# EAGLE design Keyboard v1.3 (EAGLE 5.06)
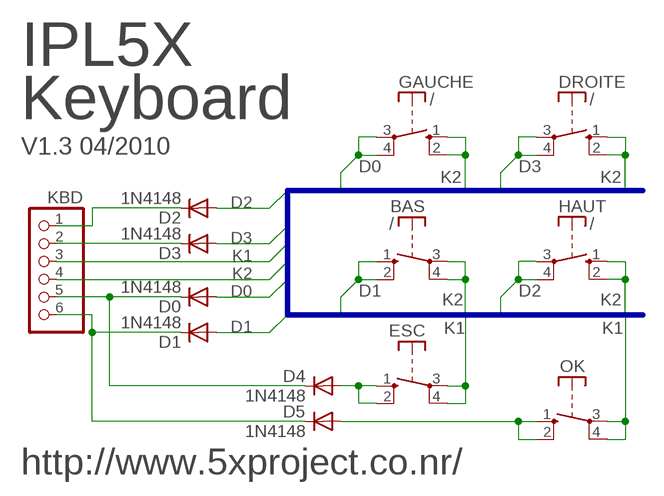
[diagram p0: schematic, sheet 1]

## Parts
BAS  /  RACON12/  [RACON12/]
D0  1N4148  1N4148DO35-7  [DO35-7]
D1  1N4148  1N4148DO35-7  [DO35-7]
D2  1N4148  1N4148DO35-7  [DO35-7]
D3  1N4148  1N4148DO35-7  [DO35-7]
D4  1N4148  1N4148DO35-7  [DO35-7]
D5  1N4148  1N4148DO35-7  [DO35-7]
DROITE  /  RACON12/  [RACON12/]
ESC  RACON12  [RACON12]
GAUCHE  /  RACON12/  [RACON12/]
HAUT  /  RACON12/  [RACON12/]
KBD  PINHD-1X6  [1X06]
OK  RACON12  [RACON12]

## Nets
D0: D0.A GAUCHE.3(P) GAUCHE.4(P)
D1: BAS.1(S) BAS.2(S) D1.A
D2: D2.A HAUT.3(P) HAUT.4(P)
D3: D3.A DROITE.3(P) DROITE.4(P)
K1: ESC.3(P) ESC.4(P) KBD.3 OK.3(P) OK.4(P)
K2: BAS.3(P) BAS.4(P) DROITE.1(S) DROITE.2(S) GAUCHE.1(S) GAUCHE.2(S) HAUT.1(S) HAUT.2(S) KBD.4
N$2: D1.C D5.C KBD.6
N$3: D0.C D4.C KBD.5
N$4: D3.C KBD.2
N$5: D2.C KBD.1
N$6: D4.A ESC.1(S) ESC.2(S)
N$7: D5.A OK.1(S) OK.2(S)

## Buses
D0,D1,D2,D3,E,RS,K1,K2

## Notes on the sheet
- IPL5X
- Keyboard
- V1.3 04/2010
- http://www.5xproject.co.nr/

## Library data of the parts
BAS DROITE ESC GAUCHE HAUT OK = switch-misc:RACON12: ITT SWITCH
D0 D1-D5 = diode:1N4148: DIODE
KBD = pinhead:PINHD-1X6: PIN HEADER

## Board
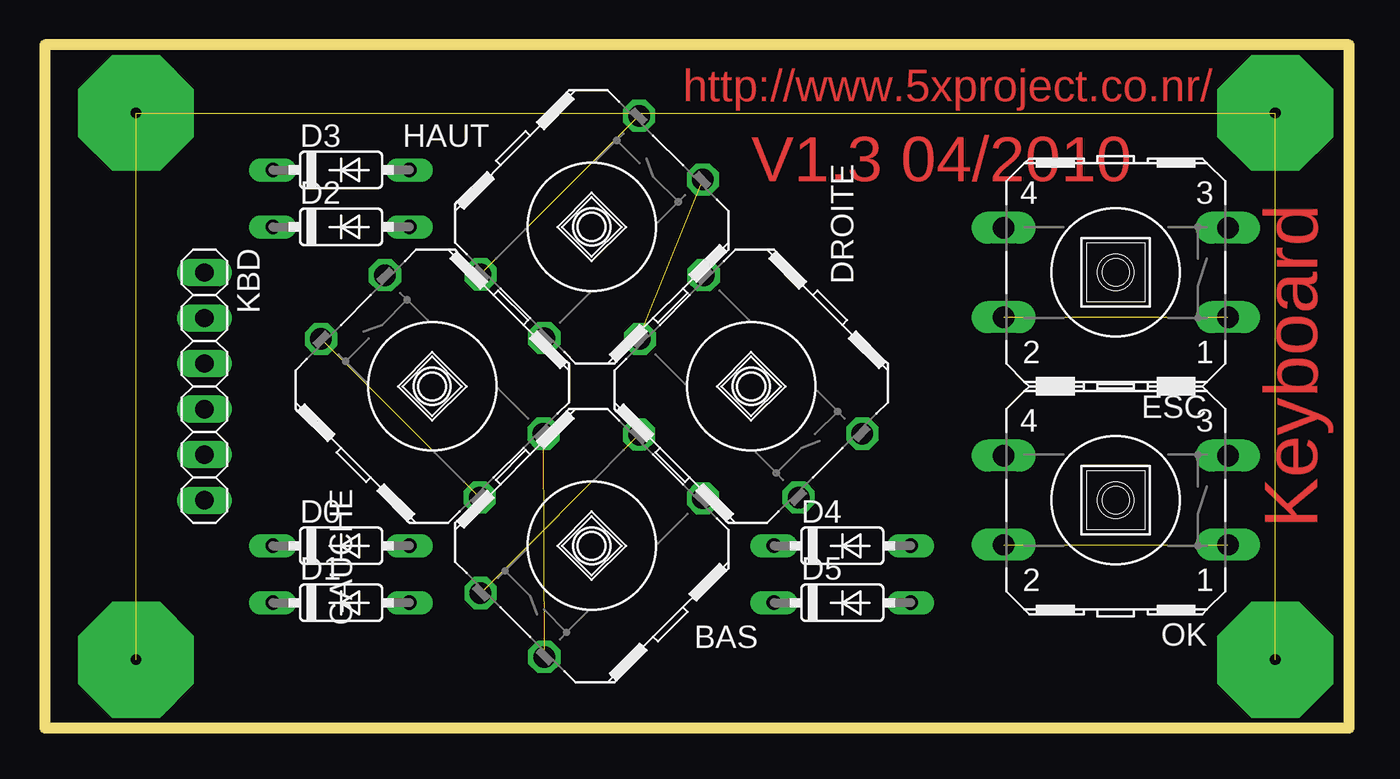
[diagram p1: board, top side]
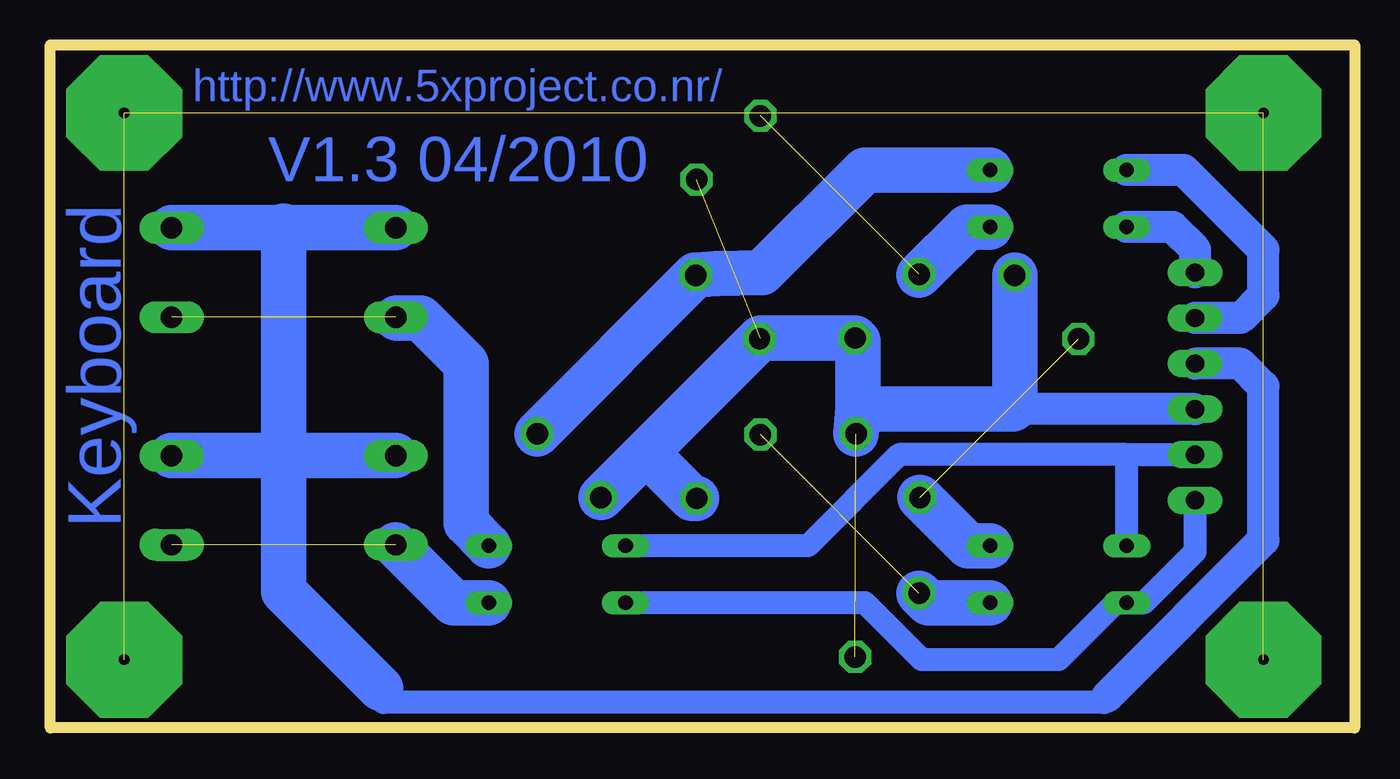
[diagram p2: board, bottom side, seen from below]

Size 72.69 x 38.09 mm. Coordinates in mm from the lower left corner, seen from the top.
Outline: 0,0 72.69,0 72.69,38.09 0,38.09 0,0
Copper layers (1*16): Top 0.035mm / dielectric 1.5mm / Bottom 0.035mm
Design rules "default": minimum track width 10mil, minimum drill 24mil, track to track 8mil, track to pad 8mil, pad to pad 8mil, via to via 8mil, smd to smd 8mil, copper to edge 40mil, drill to drill 8mil, minimum pad ring 10mil, minimum via ring 8mil, stop-mask expansion 4mil, vias tented up to drill 0mil, thermal gap 10mil

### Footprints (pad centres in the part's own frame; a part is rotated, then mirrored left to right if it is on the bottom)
RACON12/ = drill 1.194 octagon: 1 -6.198,-2.642; 2 2.642,6.198; 3 -2.642,-6.198; 4 6.198,2.642
DO35-7 = drill 0.813 long: A 3.81,0; C -3.81,0
RACON12 = drill 1.194 long: 1 -6.248,2.489; 2 6.248,2.489; 3 -6.248,-2.489; 4 6.248,-2.489
1X06 = drill 1.016 long: 1 -6.35,0; 2 -3.81,0; 3 -1.27,0; 4 1.27,0; 5 3.81,0; 6 6.35,0

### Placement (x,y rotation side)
BAS  30.48,10.16 0 top
D0  16.51,10.16 0 top
D1  16.51,6.99 0 top
D2  16.51,27.94 0 top
D3  16.51,31.11 0 top
D4  44.45,10.16 0 top
D5  44.45,6.99 0 top
DROITE  39.37,19.05 90 top
ESC  59.69,25.4 180 top
GAUCHE  21.59,19.05 270 top
HAUT  30.48,27.94 180 top
KBD  8.89,19.05 270 top
OK  59.69,12.7 180 top

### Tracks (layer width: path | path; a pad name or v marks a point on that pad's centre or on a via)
D0  (1 unrouted)
  Bottom 2.54: D0.A 21.54,10.16 GAUCHE.4
D1  (1 unrouted)
  Bottom 2.54: D1.A 23.75,6.99 BAS.1
D2  (1 unrouted)
  Bottom 1.778: 24.28,25.25 HAUT.4
  Bottom 2.54: 24.28,25.25 21.59,27.94 D2.A
D3
  Bottom 2.54: DROITE.3 DROITE.4 35.56,25.35 33.02,25.4 27.3,31.11 D3.A
K1
  Bottom 1.27: 13.81,1.75 13.97,1.43 54.13,1.43 54.29,2.22
  Bottom 1.778: KBD.3 6.35,20.32 5.08,19.05 5.08,10.48 13.81,1.75 | 59.69,10.16 59.74,10.21
  Bottom 2.54: 54.29,2.22 59.69,7.62 59.69,10.16 59.69,15.24 | 59.69,15.24 59.69,27.94 | 59.69,27.94 59.69,27.99 | ESC.4 59.64,27.89 59.69,27.94 | ESC.3 59.74,27.89 59.69,27.94 | OK.3 59.74,15.19 59.69,15.24 | OK.4 59.64,15.19 59.69,15.24
K2  (2 unrouted)
  Bottom 1.778: KBD.4 19.05,17.78 18.95,17.88 | 27.69,21.59 HAUT.2 | 33.12,21.74 DROITE.2
  Bottom 2.54: 19.05,17.78 27.69,17.78 | 27.69,17.78 GAUCHE.2 | 27.69,17.78 27.69,21.59 | HAUT.2 33.12,21.74 | 18.95,17.88 GAUCHE.1 | DROITE.2 39.5,15.37 | 39.5,15.37 DROITE.1 | BAS.4 36.93,12.8 39.5,15.37
N$1  (via drill 0.6 pad 6.45)  (3 unrouted)
  other vias: 5.08,34.29 5.08,3.81 68.58,34.29 68.58,3.81
N$2
  Bottom 1.27: KBD.6 8.89,9.84 11.75,6.99 D1.C 13.33,6.99 16.51,3.81 24.13,3.81 27.3,6.99 D5.C
N$3
  Bottom 1.27: D0.C 12.7,15.24 | 12.7,15.24 KBD.5 | D4.C 30.48,10.16 25.4,15.24 12.7,15.24
N$4
  Bottom 1.778: KBD.2 6.35,22.86 5.08,24.13 5.08,26.67 9.53,31.11 D3.C
N$5
  Bottom 1.778: KBD.1 8.89,26.67 10.16,27.94 D2.C
N$6  (1 unrouted)
  Bottom 1.27: 53.39,22.86 ESC.2
  Bottom 2.54: D4.A 49.53,11.43 49.53,20.32 52.07,22.86 53.39,22.86
N$7  (1 unrouted)
  Bottom 2.54: D5.A 50.22,6.99 OK.2

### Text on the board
Top: http://www.5xproject.co.nr/ | V1.3 04/2010 | Keyboard
Bottom: http://www.5xproject.co.nr/ | V1.3 04/2010 | Keyboard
